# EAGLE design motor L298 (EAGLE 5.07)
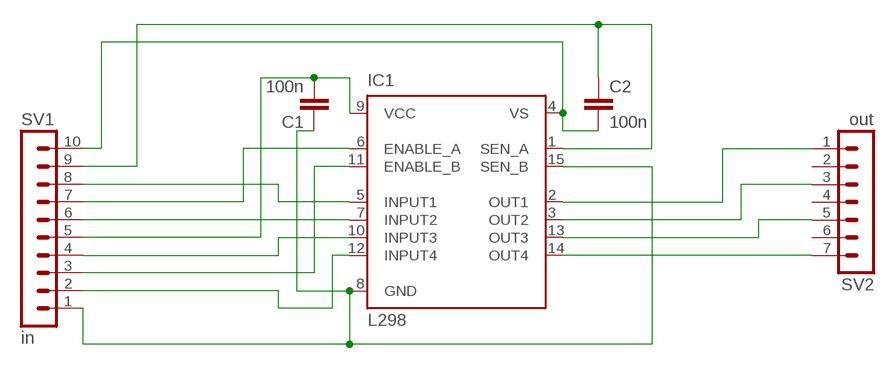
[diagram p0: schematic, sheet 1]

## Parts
C1  100n  C-EU025-050X050  [C025-050X050]
C2  100n  C-EU025-050X050  [C025-050X050]
IC1  L298  [MULTIWATT-15]
SV1  in  MA10-1  [MA10-1]
SV2  out  MA07-1  [MA07-1]

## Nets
N$1: IC1.2(OUT1) SV2.1
N$2: IC1.3(OUT2) SV2.3
N$3: IC1.13(OUT3) SV2.5
N$4: IC1.14(OUT4) SV2.7
N$5: C1.2 IC1.9(VCC) SV1.5
N$6: C2.1 IC1.1(SEN_A) SV1.9
N$7: C2.2 IC1.4(VS) SV1.10
N$8: C1.1 IC1.8(GND) IC1.15(SEN_B) SV1.1
N$9: IC1.7(INPUT2) SV1.6
N$10: IC1.10(INPUT3) SV1.4
N$11: IC1.6(ENABLE_A) SV1.7
N$12: IC1.11(ENABLE_B) SV1.3
N$14: IC1.12(INPUT4) SV1.2
N$15: IC1.5(INPUT1) SV1.8
Unconnected: SV2.2 SV2.4 SV2.6

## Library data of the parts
C1 C2 = resistor:C-EU: CAPACITOR, European symbol
IC1 = st-microelectronics:L298: DUAL FULL-BRIDGE DRIVER
SV1 = con-lstb:MA10-1: PIN HEADER
SV2 = con-lstb:MA07-1: PIN HEADER

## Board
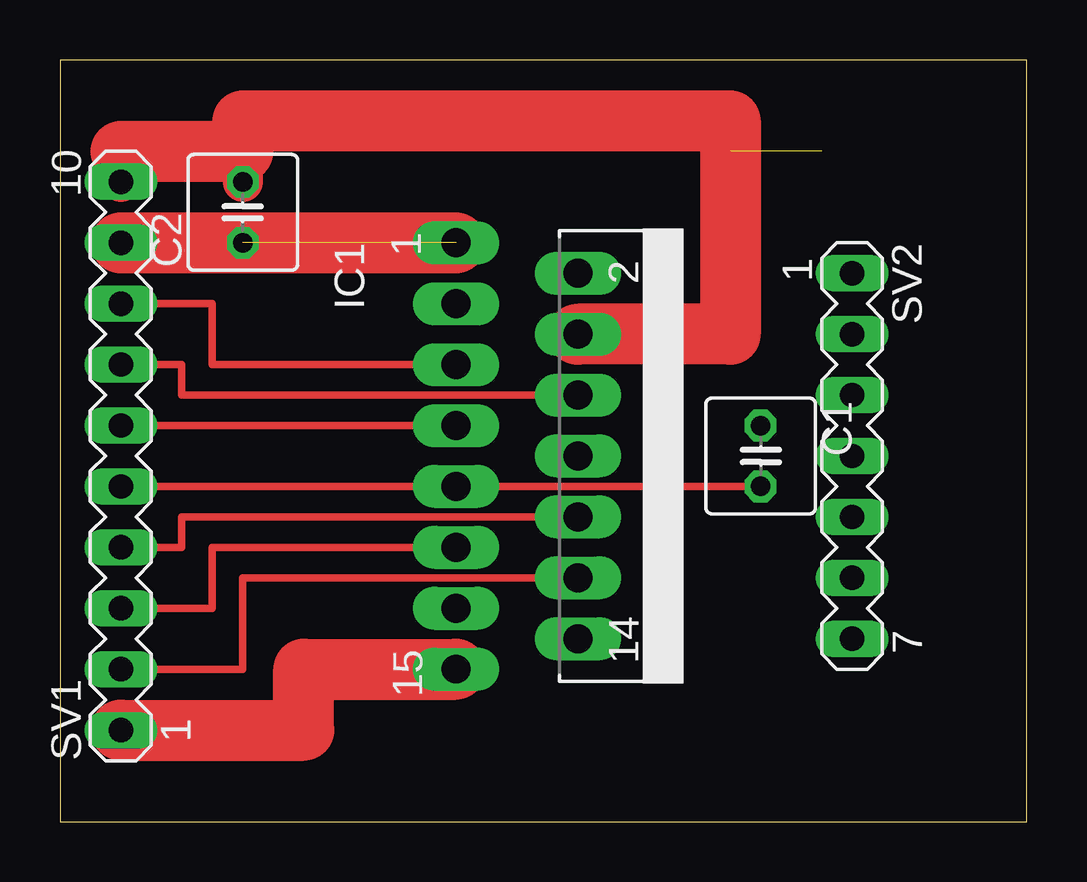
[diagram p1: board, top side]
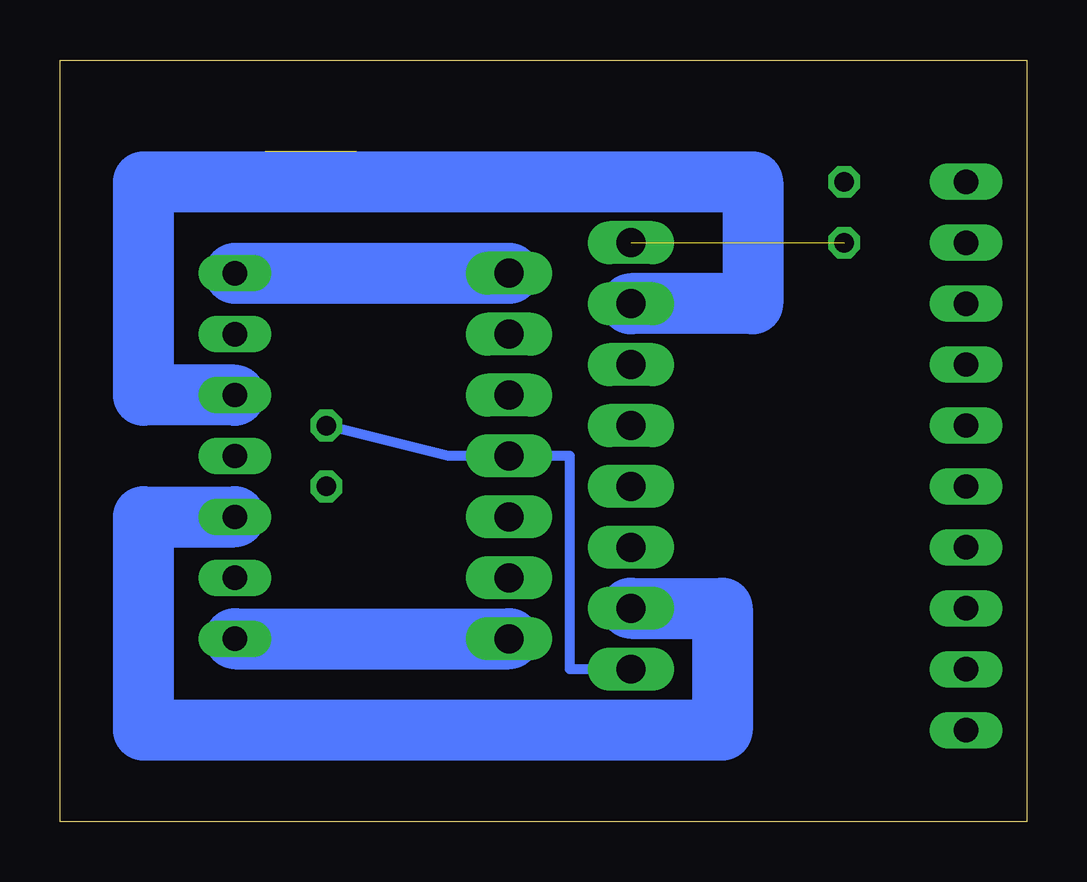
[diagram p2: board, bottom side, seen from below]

Size 40.31 x 31.74 mm. Coordinates in mm from the lower left corner, seen from the top.
Outline: 0,0 40.31,0 40.31,31.74 0,31.74 0,0
Copper layers (1*16): Top 0.035mm / dielectric 1.5mm / Bottom 0.035mm
Design rules "default": minimum track width 10mil, minimum drill 24mil, track to track 8mil, track to pad 8mil, pad to pad 8mil, via to via 8mil, smd to smd 8mil, copper to edge 40mil, drill to drill 8mil, minimum pad ring 10mil, minimum via ring 8mil, stop-mask expansion 4mil, vias tented up to drill 0mil, thermal gap 10mil

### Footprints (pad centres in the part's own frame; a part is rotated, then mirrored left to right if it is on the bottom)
C025-050X050 = drill 0.813 octagon: 1 -1.27,0; 2 1.27,0
MULTIWATT-15 = drill 1.2 long: 1 -8.89,-7.62; 2 -7.62,-2.54; 3 -6.35,-7.62; 4 -5.08,-2.54; 5 -3.81,-7.62; 6 -2.54,-2.54; 7 -1.27,-7.62; 8 0,-2.54; 9 1.27,-7.62; 10 2.54,-2.54; 11 3.81,-7.62; 12 5.08,-2.54; 13 6.35,-7.62; 14 7.62,-2.54; 15 8.89,-7.62
MA10-1 = drill 1.016 long: 1 -11.43,0; 2 -8.89,0; 3 -6.35,0; 4 -3.81,0; 5 -1.27,0; 6 1.27,0; 7 3.81,0; 8 6.35,0; 9 8.89,0; 10 11.43,0
MA07-1 = drill 1.016 long: 1 -7.62,0; 2 -5.08,0; 3 -2.54,0; 4 0,0; 5 2.54,0; 6 5.08,0; 7 7.62,0

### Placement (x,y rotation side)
C1  29.21,15.24 270 top
C2  7.62,25.4 90 top
IC1  24.13,15.24 270 top
SV1  2.54,15.24 90 top
SV2  33.02,15.24 270 top

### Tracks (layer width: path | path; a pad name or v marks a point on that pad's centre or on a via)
N$1
  Bottom 2.54: SV2.1 IC1.2
N$2
  Bottom 2.54: SV2.3 36.83,17.78 36.83,26.67 11.43,26.67 11.43,21.59 IC1.3
N$3
  Bottom 2.54: IC1.13 12.7,8.89 12.7,3.81 36.83,3.81 36.83,12.7 SV2.5
N$4
  Bottom 2.54: SV2.7 IC1.14
N$5
  Top 0.305: C1.2 IC1.9 SV1.5
N$6  (1 unrouted)
  Top 2.54: SV1.9 IC1.1
N$7
  Top 1.676: SV1.10 2.54,27.94 | 7.62,27.94 C2.2
  Top 2.54: IC1.4 27.94,20.32 27.94,29.21 7.62,29.21 7.62,27.94 2.54,27.94
N$8
  Top 2.54: SV1.1 10.16,3.81 10.16,6.35 IC1.15
  Bottom 0.406: C1.1 24.13,15.24 IC1.8 19.05,15.24 19.05,6.35 IC1.15
N$9
  Top 0.305: IC1.7 SV1.6
N$10
  Top 0.305: IC1.10 5.08,12.7 5.08,11.43 SV1.4
N$11
  Top 0.305: IC1.6 5.08,17.78 5.08,19.05 SV1.7
N$12
  Top 0.305: IC1.11 6.35,11.43 6.35,8.89 SV1.3
N$13  (1 unrouted)
N$14
  Top 0.305: IC1.12 7.62,10.16 7.62,6.35 SV1.2
N$15
  Top 0.305: IC1.5 6.35,19.05 6.35,21.59 SV1.8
